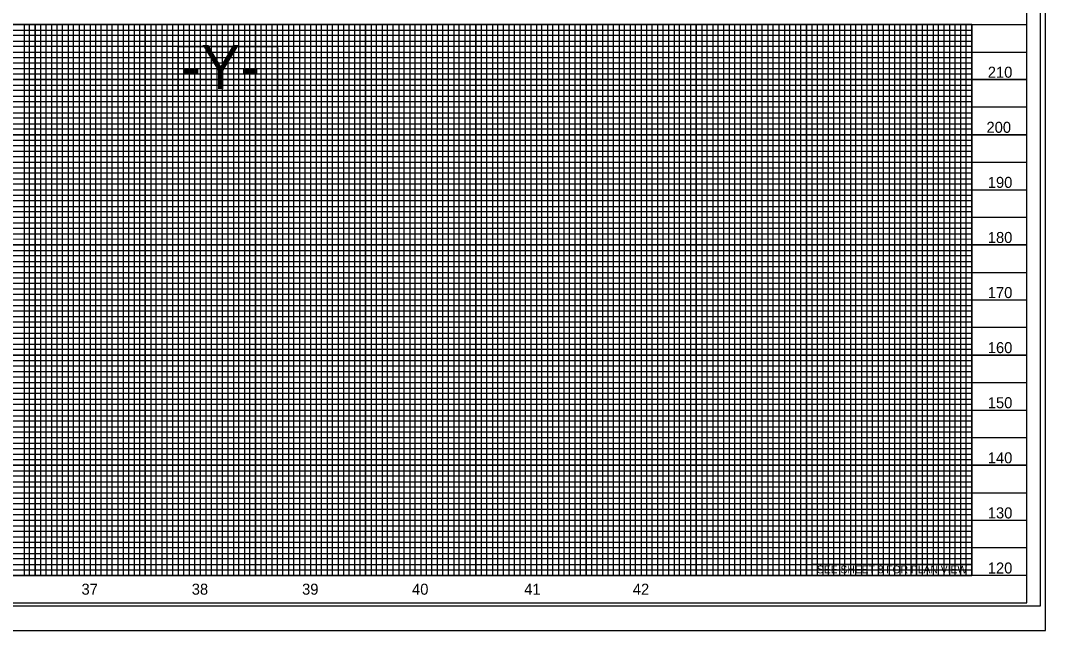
# Model space of a CAD drawing. Extents: x 1779926 to 1781610, y 620464 to 621564.
# Drawn here: x 1780680 to 1781610, y 620464 to 621018 of the extents above; entities that cross this region are included whole.
import ezdxf

# ---------------------------------------------------------------- set-up
doc = ezdxf.new("R2010")
doc.units = 0
for name, color, linetype in [('Exist Vertical Profile Horizontal Axis Label Major', 7, 'Continuous'), ('Exist Vertical Profile Vertical Axis Label', 7, 'Continuous'), ('Prop DSN Text', 7, 'Continuous'), ('Prop Grid Mask', 7, 'Continuous'), ('Scratch_Level_0', 7, 'Continuous'), ('Sheet Cutting Line CELL', 7, 'Continuous'), ('Sheet DOT Grid CELL', 7, 'Continuous'), ('Sheet Layout Profile Border Port 2', 7, 'Continuous'), ('Sheet Plot Border Inside CELL', 7, 'Continuous'), ('Sheet Plot Border Outside CELL', 7, 'Continuous'), ('Sheet Profile CELL', 7, 'Continuous'), ('Sheet Profile Grid Major CELL', 7, 'Continuous'), ('Sheet Profile Grid Middle CELL', 7, 'Continuous'), ('Sheet Profile Grid Minor CELL', 7, 'Continuous')]:
    doc.layers.add(name, color=color, linetype=linetype)

msp = doc.modelspace()

# ---------------------------------------------------------------- linework, layer by layer
at = {"layer": 'Prop Grid Mask'}
for points in [[(1780822.96, 620994.19), (1780912.96, 620994.19), (1780912.96, 620954.19), (1780822.96, 620954.19)], [(1781542.96, 620524.19), (1781397.96, 620524.19), (1781397.96, 620514.19), (1781542.96, 620514.19)]]:
    msp.add_lwpolyline(points, close=True, dxfattribs=at)
at = {"layer": 'Scratch_Level_0'}
msp.add_lwpolyline([(1780142.96, 620514.19), (1780142.96, 621014.19), (1781542.96, 621014.19), (1781542.96, 620514.19)], close=True, dxfattribs=at)
at = {"layer": 'Sheet Cutting Line CELL'}
msp.add_line((1779925.96, 620464.19), (1781609.96, 620464.19), dxfattribs=at)
at = {"layer": 'Sheet DOT Grid CELL'}
for p, q in [((1780092.96, 621014.19), (1781592.85, 621014.19)), ((1780692.96, 621014.19), (1780692.96, 620514.19)), ((1780742.96, 621014.19), (1780742.96, 620514.19)), ((1780792.96, 621014.19), (1780792.96, 620514.19)), ((1780842.96, 621014.19), (1780842.96, 620514.19)), ((1780892.96, 621014.19), (1780892.96, 620514.19)), ((1780942.96, 621014.19), (1780942.96, 620514.19)), ((1780992.96, 621014.19), (1780992.96, 620514.19)), ((1781042.96, 621014.19), (1781042.96, 620514.19)), ((1781092.96, 621014.19), (1781092.96, 620514.19)), ((1781142.96, 621014.19), (1781142.96, 620514.19)), ((1781192.96, 621014.19), (1781192.96, 620514.19)), ((1781242.96, 621014.19), (1781242.96, 620514.19)), ((1781292.96, 621014.19), (1781292.96, 620514.19)), ((1781342.96, 621014.19), (1781342.96, 620514.19)), ((1781392.96, 621014.19), (1781392.96, 620514.19)), ((1781442.96, 621014.19), (1781442.96, 620514.19)), ((1781492.96, 621014.19), (1781492.96, 620514.19)), ((1781542.96, 621014.19), (1781542.96, 620514.19)), ((1780092.96, 620964.19), (1781592.85, 620964.19)), ((1780092.96, 620914.19), (1781592.85, 620914.19)), ((1780092.96, 620864.19), (1781592.85, 620864.19)), ((1780092.96, 620814.19), (1781592.85, 620814.19)), ((1780092.96, 620764.19), (1781592.85, 620764.19)), ((1780092.96, 620714.19), (1781592.85, 620714.19)), ((1780092.96, 620664.19), (1781592.85, 620664.19)), ((1780092.96, 620614.19), (1781592.85, 620614.19)), ((1780092.96, 620564.19), (1781592.85, 620564.19))]:
    msp.add_line(p, q, dxfattribs=at)
at = {"layer": 'Sheet Layout Profile Border Port 2'}
for points in [[(1780142.96, 621014.19), (1781542.96, 621014.19), (1781542.96, 620514.19), (1780142.96, 620514.19)], [(1781542.96, 621014.19), (1780232.96, 621014.19), (1780232.96, 620514.19), (1781542.96, 620514.19)]]:
    msp.add_lwpolyline(points, close=True, dxfattribs=at)
at = {"layer": 'Sheet Plot Border Inside CELL'}
msp.add_lwpolyline([(1779938.96, 620486.64), (1781605.46, 620486.64), (1781605.46, 621541.74), (1779938.96, 621541.74)], close=True, dxfattribs=at)
at = {"layer": 'Sheet Plot Border Outside CELL'}
msp.add_lwpolyline([(1779925.96, 620464.19), (1781609.96, 620464.19), (1781609.96, 621564.19), (1779925.96, 621564.19)], close=True, dxfattribs=at)
at = {"layer": 'Sheet Profile CELL'}
for p, q in [((1780092.96, 621014.19), (1781592.96, 621014.19)), ((1781592.96, 620514.19), (1780092.96, 620514.19)), ((1780092.96, 620489.19), (1781592.96, 620489.19))]:
    msp.add_line(p, q, dxfattribs=at)
msp.add_lwpolyline([(1781592.96, 621539.19), (1780092.96, 621539.19), (1780092.96, 620489.19), (1781592.96, 620489.19)], close=True, dxfattribs=at)
at = {"layer": 'Sheet Profile Grid Major CELL'}
for p, q in [((1780692.96, 621014.19), (1780742.96, 621014.19)), ((1780792.96, 621014.19), (1780842.96, 621014.19)), ((1780892.96, 621014.19), (1780942.96, 621014.19)), ((1780992.96, 621014.19), (1781042.96, 621014.19)), ((1781092.96, 621014.19), (1781142.96, 621014.19)), ((1781192.96, 621014.19), (1781242.96, 621014.19)), ((1781292.96, 621014.19), (1781342.96, 621014.19)), ((1781392.96, 621014.19), (1781442.96, 621014.19)), ((1781492.96, 621014.19), (1781542.96, 621014.19)), ((1781492.96, 620514.19), (1781492.96, 620514.19))]:
    msp.add_line(p, q, dxfattribs=at)
for points in [[(1780642.96, 620514.19), (1780692.96, 620514.19), (1780692.96, 621014.19), (1780742.96, 621014.19), (1780742.96, 620514.19), (1780792.96, 620514.19), (1780792.96, 621014.19), (1780842.96, 621014.19), (1780842.96, 620514.19), (1780892.96, 620514.19), (1780892.96, 621014.19), (1780942.96, 621014.19), (1780942.96, 620514.19), (1780992.96, 620514.19), (1780992.96, 621014.19), (1781042.96, 621014.19), (1781042.96, 620514.19), (1781092.96, 620514.19), (1781092.96, 621014.19), (1781142.96, 621014.19), (1781142.96, 620514.19), (1781192.96, 620514.19), (1781192.96, 621014.19), (1781242.96, 621014.19), (1781242.96, 620514.19), (1781292.96, 620514.19), (1781292.96, 621014.19), (1781342.96, 621014.19), (1781342.96, 620514.19), (1781392.96, 620514.19), (1781392.96, 621014.19), (1781442.96, 621014.19), (1781442.96, 620514.19), (1781492.96, 620514.19), (1781492.96, 620514.19), (1781492.96, 621014.19), (1781542.96, 621014.19), (1781542.96, 620514.19)], [(1781592.96, 620964.19), (1780092.96, 620964.19)], [(1781592.96, 620914.19), (1780092.96, 620914.19), (1780092.96, 620864.19), (1781592.96, 620864.19)], [(1781592.96, 620814.19), (1780092.96, 620814.19), (1780092.96, 620764.19), (1781592.96, 620764.19)], [(1781592.96, 620714.19), (1780092.96, 620714.19), (1780092.96, 620664.19), (1781592.96, 620664.19)], [(1781592.96, 620614.19), (1780092.96, 620614.19), (1780092.96, 620614.19), (1780092.96, 620564.19), (1781592.96, 620564.19)], [(1781592.96, 620514.19), (1780092.96, 620514.19)]]:
    msp.add_lwpolyline(points, dxfattribs=at)
at = {"layer": 'Sheet Profile Grid Middle CELL'}
for points in [[(1780667.96, 620514.19), (1780717.96, 620514.19), (1780717.96, 620514.19), (1780717.96, 621014.19), (1780767.96, 621014.19), (1780767.96, 620514.19), (1780817.96, 620514.19), (1780817.96, 621014.19), (1780867.96, 621014.19), (1780867.96, 620514.19), (1780917.96, 620514.19), (1780917.96, 621014.19), (1780967.96, 621014.19), (1780967.96, 620514.19), (1781017.96, 620514.19), (1781017.96, 621014.19), (1781067.96, 621014.19), (1781067.96, 620514.19), (1781117.96, 620514.19), (1781117.96, 621014.19), (1781167.96, 621014.19), (1781167.96, 620514.19), (1781217.96, 620514.19), (1781217.96, 621014.19), (1781267.96, 621014.19), (1781267.96, 620514.19), (1781317.96, 620514.19), (1781317.96, 621014.19), (1781367.96, 621014.19), (1781367.96, 620514.19), (1781417.96, 620514.19), (1781417.96, 621014.19), (1781467.96, 621014.19), (1781467.96, 620514.19), (1781517.96, 620514.19), (1781517.96, 621014.19)], [(1780092.96, 620989.19), (1781592.96, 620989.19)], [(1781592.96, 620939.19), (1780092.96, 620939.19), (1780092.96, 620889.19), (1781592.96, 620889.19)], [(1781592.96, 620839.19), (1780092.96, 620839.19), (1780092.96, 620789.19), (1781592.96, 620789.19)], [(1781592.96, 620739.19), (1780092.96, 620739.19), (1780092.96, 620689.19), (1781592.96, 620689.19)], [(1781592.96, 620639.19), (1780092.96, 620639.19), (1780092.96, 620589.19), (1781592.96, 620589.19)], [(1781592.96, 620539.19), (1780092.96, 620539.19)]]:
    msp.add_lwpolyline(points, dxfattribs=at)
at = {"layer": 'Sheet Profile Grid Minor CELL'}
for p, q in [((1780142.96, 621009.19), (1781542.96, 621009.19)), ((1781542.96, 621004.19), (1780142.96, 621004.19)), ((1780142.96, 620999.19), (1781542.96, 620999.19)), ((1781542.96, 620994.19), (1780142.96, 620994.19)), ((1780142.96, 620984.19), (1781542.96, 620984.19)), ((1781542.96, 620979.19), (1780142.96, 620979.19)), ((1780142.96, 620974.19), (1781542.96, 620974.19)), ((1781542.96, 620969.19), (1780142.96, 620969.19)), ((1780142.96, 620959.19), (1781542.96, 620959.19)), ((1781542.96, 620954.19), (1780142.96, 620954.19)), ((1780142.96, 620949.19), (1781542.96, 620949.19)), ((1781542.96, 620944.19), (1780142.96, 620944.19)), ((1780142.96, 620934.19), (1781542.96, 620934.19)), ((1781542.96, 620929.19), (1780142.96, 620929.19)), ((1780142.96, 620924.19), (1781542.96, 620924.19)), ((1781542.96, 620919.19), (1780142.96, 620919.19)), ((1780142.96, 620909.19), (1781542.96, 620909.19)), ((1781542.96, 620904.19), (1780142.96, 620904.19)), ((1780142.96, 620899.19), (1781542.96, 620899.19)), ((1781542.96, 620894.19), (1780142.96, 620894.19)), ((1780142.96, 620884.19), (1781542.96, 620884.19)), ((1781542.96, 620879.19), (1780142.96, 620879.19)), ((1780142.96, 620874.19), (1781542.96, 620874.19)), ((1781542.96, 620869.19), (1780142.96, 620869.19)), ((1780142.96, 620859.19), (1781542.96, 620859.19)), ((1781542.96, 620854.19), (1780142.96, 620854.19)), ((1780142.96, 620849.19), (1781542.96, 620849.19)), ((1781542.96, 620844.19), (1780142.96, 620844.19)), ((1780142.96, 620834.19), (1781542.96, 620834.19)), ((1781542.96, 620829.19), (1780142.96, 620829.19)), ((1780142.96, 620824.19), (1781542.96, 620824.19)), ((1781542.96, 620819.19), (1780142.96, 620819.34)), ((1780142.96, 620809.19), (1781542.96, 620809.19)), ((1781542.96, 620804.19), (1780142.96, 620804.19)), ((1780142.96, 620799.19), (1781542.96, 620799.19)), ((1781542.96, 620794.19), (1780142.96, 620794.19)), ((1780142.96, 620784.19), (1781542.96, 620784.19)), ((1781542.96, 620779.19), (1780142.96, 620779.19)), ((1780142.96, 620774.19), (1781542.96, 620774.19)), ((1781542.96, 620769.19), (1780142.96, 620769.19)), ((1780142.96, 620759.19), (1781542.96, 620759.19)), ((1781542.96, 620754.19), (1780142.96, 620754.19)), ((1780142.96, 620749.19), (1781542.96, 620749.19)), ((1781542.96, 620744.19), (1780142.96, 620744.19)), ((1780142.96, 620734.19), (1781542.96, 620734.19)), ((1781542.96, 620729.19), (1780142.96, 620729.19)), ((1780142.96, 620724.19), (1781542.96, 620724.19)), ((1781542.96, 620719.19), (1780142.96, 620719.19)), ((1780142.96, 620709.19), (1781542.96, 620709.19)), ((1781542.96, 620704.19), (1780142.96, 620704.19)), ((1780142.96, 620699.19), (1781542.96, 620699.19)), ((1781542.96, 620694.19), (1780142.96, 620694.19)), ((1780142.96, 620684.19), (1781542.96, 620684.19)), ((1781542.96, 620679.19), (1780142.96, 620679.19)), ((1780142.96, 620674.19), (1781542.96, 620674.19)), ((1781542.96, 620669.19), (1780142.96, 620669.19)), ((1780142.96, 620659.19), (1781542.96, 620659.19)), ((1781542.96, 620654.19), (1780142.96, 620654.19)), ((1780142.96, 620649.19), (1781542.96, 620649.19)), ((1781542.96, 620644.19), (1780142.96, 620644.19)), ((1780142.96, 620634.19), (1781542.96, 620634.19)), ((1781542.96, 620629.19), (1780142.96, 620629.19)), ((1780142.96, 620624.19), (1781542.96, 620624.19)), ((1781542.96, 620619.19), (1780142.96, 620619.19)), ((1780142.96, 620609.19), (1781542.96, 620609.19)), ((1781542.96, 620604.19), (1780142.96, 620604.19)), ((1780142.96, 620599.19), (1781542.96, 620599.19)), ((1781542.96, 620594.19), (1780142.96, 620594.19)), ((1780142.96, 620584.19), (1781542.96, 620584.19)), ((1781542.96, 620579.19), (1780142.96, 620579.19)), ((1780142.96, 620574.19), (1781542.96, 620574.19)), ((1781542.96, 620569.19), (1780142.96, 620569.19)), ((1780142.96, 620559.19), (1781542.96, 620559.19)), ((1781542.96, 620554.19), (1780142.96, 620554.19)), ((1780142.96, 620549.19), (1781542.96, 620549.19)), ((1781542.96, 620544.19), (1780142.96, 620544.19)), ((1780142.96, 620534.19), (1781542.96, 620534.19)), ((1781542.96, 620529.19), (1780142.96, 620529.19)), ((1780142.96, 620524.19), (1781542.96, 620524.19)), ((1780142.96, 620519.19), (1781542.96, 620519.19)), ((1781542.96, 620519.19), (1781542.96, 620519.19))]:
    msp.add_line(p, q, dxfattribs=at)
for points in [[(1780677.96, 621014.19), (1780682.96, 621014.19), (1780682.96, 620514.19), (1780687.96, 620514.19), (1780687.96, 621014.19), (1780697.96, 621014.19), (1780697.96, 620514.19), (1780702.96, 620514.19), (1780702.96, 621014.19), (1780707.96, 621014.19), (1780707.96, 620514.19), (1780712.96, 620514.19), (1780712.96, 621014.19), (1780722.96, 621014.19), (1780722.96, 620514.19), (1780727.96, 620514.19), (1780727.96, 621014.19), (1780732.96, 621014.19), (1780732.96, 620514.19), (1780737.96, 620514.19), (1780737.96, 621014.19), (1780747.96, 621014.19), (1780747.96, 620514.19), (1780752.96, 620514.19), (1780752.96, 621014.19), (1780757.96, 621014.19), (1780757.96, 620514.19), (1780762.96, 620514.19), (1780762.96, 621014.19), (1780772.96, 621014.19), (1780772.96, 620514.19), (1780777.96, 620514.19), (1780777.96, 621014.19), (1780782.96, 621014.19), (1780782.96, 620514.19), (1780787.96, 620514.19), (1780787.96, 621014.19), (1780797.96, 621014.19), (1780797.96, 620514.19), (1780797.96, 620514.19), (1780802.96, 620514.19), (1780802.96, 621014.19), (1780807.96, 621014.19), (1780807.96, 620514.19), (1780812.96, 620514.19), (1780812.96, 621014.19), (1780822.96, 621014.19), (1780822.96, 620514.19), (1780827.96, 620514.19), (1780827.96, 621014.19), (1780832.96, 621014.19), (1780832.96, 620514.19), (1780837.96, 620514.19), (1780837.96, 621014.19), (1780847.96, 621014.19), (1780847.96, 620514.19), (1780852.96, 620514.19), (1780852.96, 621014.19), (1780857.96, 621014.19), (1780857.96, 620514.19), (1780862.96, 620514.19), (1780862.96, 621014.19), (1780872.96, 621014.19), (1780872.96, 620514.19), (1780877.96, 620514.19), (1780877.96, 621014.19), (1780882.96, 621014.19), (1780882.96, 620514.19), (1780887.96, 620514.19), (1780887.96, 621014.19), (1780897.96, 621014.19), (1780897.96, 620514.19), (1780902.96, 620514.19), (1780902.96, 621014.19), (1780907.96, 621014.19), (1780907.96, 620514.19), (1780912.96, 620514.19), (1780912.96, 621014.19), (1780922.96, 621014.19), (1780922.96, 620514.19), (1780927.96, 620514.19), (1780927.96, 621014.19), (1780932.96, 621014.19), (1780932.96, 620514.19), (1780937.96, 620514.19), (1780937.96, 621014.19), (1780947.96, 621014.19), (1780947.96, 620514.19), (1780952.66, 620514.74), (1780952.96, 620514.19), (1780952.96, 621014.19), (1780957.96, 621014.19), (1780957.96, 620514.19), (1780962.96, 620514.19), (1780962.96, 621014.19), (1780972.96, 621014.19), (1780972.96, 620514.19), (1780977.96, 620514.19)], [(1780977.96, 620514.19), (1780977.96, 621014.19), (1780982.96, 621014.19), (1780982.96, 620514.19), (1780987.96, 620514.19), (1780987.96, 621014.19), (1780997.96, 621014.19), (1780997.96, 620514.19), (1781002.96, 620514.19), (1781002.96, 621014.19), (1781007.96, 621014.19), (1781007.96, 620514.19), (1781012.96, 620514.19), (1781012.96, 621014.19), (1781022.96, 621014.19), (1781022.96, 620514.19), (1781027.96, 620514.19), (1781027.96, 621014.19), (1781032.96, 621014.19), (1781032.96, 620514.19), (1781037.96, 620514.19), (1781037.96, 621014.19), (1781047.96, 621014.19), (1781047.96, 620514.19), (1781052.96, 620514.19), (1781052.96, 621014.19), (1781057.96, 621014.19), (1781057.96, 620514.19), (1781062.96, 620514.19), (1781062.96, 621014.19), (1781072.96, 621014.19), (1781072.96, 620514.19), (1781077.96, 620514.19), (1781077.96, 621014.19), (1781082.96, 621014.19), (1781082.96, 620514.19), (1781087.96, 620514.19), (1781087.96, 621014.19), (1781097.96, 621014.19), (1781097.96, 620514.19), (1781102.96, 620514.19), (1781102.96, 621014.19), (1781107.96, 621014.19), (1781107.96, 620514.19), (1781112.96, 620514.19), (1781112.96, 621014.19), (1781122.96, 621014.19), (1781122.96, 620514.19), (1781127.96, 620514.19), (1781127.96, 621014.19), (1781132.96, 621014.19), (1781132.96, 620514.19), (1781137.96, 620514.19), (1781137.96, 621014.19), (1781147.96, 621014.19), (1781147.96, 620514.19), (1781152.96, 620514.19), (1781152.96, 621014.19), (1781157.96, 621014.19), (1781157.96, 620514.19), (1781162.96, 620514.19), (1781162.96, 621014.19), (1781172.96, 621014.19), (1781172.96, 620514.19), (1781177.96, 620514.19), (1781177.96, 621014.19), (1781182.96, 621014.19), (1781182.96, 620514.19), (1781187.96, 620514.19), (1781187.96, 621014.19), (1781197.96, 621014.19), (1781197.96, 620514.19), (1781202.96, 620514.19), (1781202.96, 621014.19), (1781207.96, 621014.19), (1781207.96, 620514.19), (1781212.96, 620514.19), (1781212.96, 621014.19), (1781222.96, 621014.19), (1781222.96, 620514.19), (1781227.96, 620514.19), (1781227.96, 621014.19), (1781232.96, 621014.19), (1781232.96, 620514.19), (1781237.96, 620514.19), (1781237.96, 621014.19), (1781247.96, 621014.19), (1781247.96, 620514.19), (1781252.96, 620514.19), (1781252.96, 621014.19), (1781257.96, 621014.19), (1781257.96, 620514.19), (1781262.96, 620514.19), (1781262.96, 621014.19), (1781272.96, 621014.19), (1781272.96, 620514.19), (1781277.96, 620514.19), (1781277.96, 621014.19), (1781282.96, 621014.19), (1781282.96, 620514.19)], [(1781282.96, 620514.19), (1781287.96, 620514.19), (1781287.96, 621014.19), (1781297.96, 621014.19), (1781297.96, 620514.19), (1781302.96, 620514.19), (1781302.96, 621014.19), (1781307.96, 621014.19), (1781307.96, 620514.19), (1781312.96, 620514.19), (1781312.96, 621014.19), (1781322.96, 621014.19), (1781322.96, 620514.19), (1781327.96, 620514.19), (1781327.96, 621014.19), (1781332.96, 621014.19), (1781332.96, 620514.19), (1781337.96, 620514.19), (1781337.96, 621014.19), (1781347.96, 621014.19), (1781347.96, 620514.19), (1781352.96, 620514.19), (1781352.96, 621014.19), (1781357.96, 621014.19), (1781357.96, 620514.19), (1781362.96, 620514.19), (1781362.96, 621014.19), (1781372.96, 621014.19), (1781372.96, 620514.19), (1781377.96, 620514.19), (1781377.96, 621014.19), (1781382.96, 621014.19), (1781382.96, 620514.19), (1781387.96, 620514.19), (1781387.96, 621014.19), (1781397.96, 621014.19), (1781397.96, 620514.19), (1781402.96, 620514.19), (1781402.96, 621014.19), (1781407.96, 621014.19), (1781407.96, 620514.19), (1781412.96, 620514.19), (1781412.96, 621014.19), (1781422.96, 621014.19), (1781422.96, 620514.19), (1781427.96, 620514.19), (1781427.96, 621014.19), (1781432.96, 621014.19), (1781432.96, 620514.19), (1781437.96, 620514.19), (1781437.96, 621014.19), (1781447.96, 621014.19), (1781447.96, 620514.19), (1781452.96, 620514.19), (1781452.96, 621014.19), (1781457.96, 621014.19), (1781457.96, 620514.19), (1781462.96, 620514.19), (1781462.96, 621014.19), (1781472.96, 621014.19), (1781472.96, 620514.19), (1781477.96, 620514.19), (1781477.96, 621014.19), (1781482.96, 621014.19), (1781482.96, 620514.19), (1781487.96, 620514.19), (1781487.96, 621014.19), (1781497.96, 621014.19), (1781497.96, 620514.19), (1781502.96, 620514.19), (1781502.96, 621014.19), (1781507.96, 621014.19), (1781507.96, 620514.19), (1781512.96, 620514.19), (1781512.96, 621014.19), (1781522.96, 621014.19), (1781522.96, 620514.19), (1781527.96, 620514.19), (1781527.96, 621014.19), (1781532.96, 621014.19), (1781532.96, 620514.19), (1781537.96, 620514.19), (1781537.96, 621014.19), (1781542.96, 621014.19)]]:
    msp.add_lwpolyline(points, dxfattribs=at)

# ---------------------------------------------------------------- texts
at = {"layer": 'Exist Vertical Profile Horizontal Axis Label Major'}
for s, p in [('37', (1780735.12, 620496.69)), ('38', (1780835.17, 620496.69)), ('39', (1780935.29, 620496.69)), ('40', (1781035.09, 620496.69)), ('41', (1781136.88, 620496.69)), ('42', (1781235.45, 620496.69))]:
    msp.add_text(s, height=10, dxfattribs=at).set_placement(p)
at = {"layer": 'Exist Vertical Profile Vertical Axis Label'}
for s, height, p in [('-Y-', 40, (1780825.81, 620955.78)), ('210', 10, (1781557.59, 620965.93)), ('200', 10, (1781556.39, 620915.93)), ('190', 10, (1781557.59, 620865.93)), ('180', 10, (1781557.59, 620815.93)), ('170', 10, (1781557.59, 620765.93)), ('160', 10, (1781557.59, 620715.93)), ('150', 10, (1781557.59, 620665.93)), ('140', 10, (1781557.59, 620615.93)), ('130', 10, (1781557.59, 620565.93)), ('120', 10, (1781557.59, 620515.93))]:
    msp.add_text(s, height=height, dxfattribs=at).set_placement(p)
at = {"layer": 'Prop DSN Text'}
msp.add_text('SEE SHEET 8 FOR PLAN VIEW', height=7, dxfattribs=at).set_placement((1781402.54, 620516.14))

doc.saveas('drawing.dxf')
